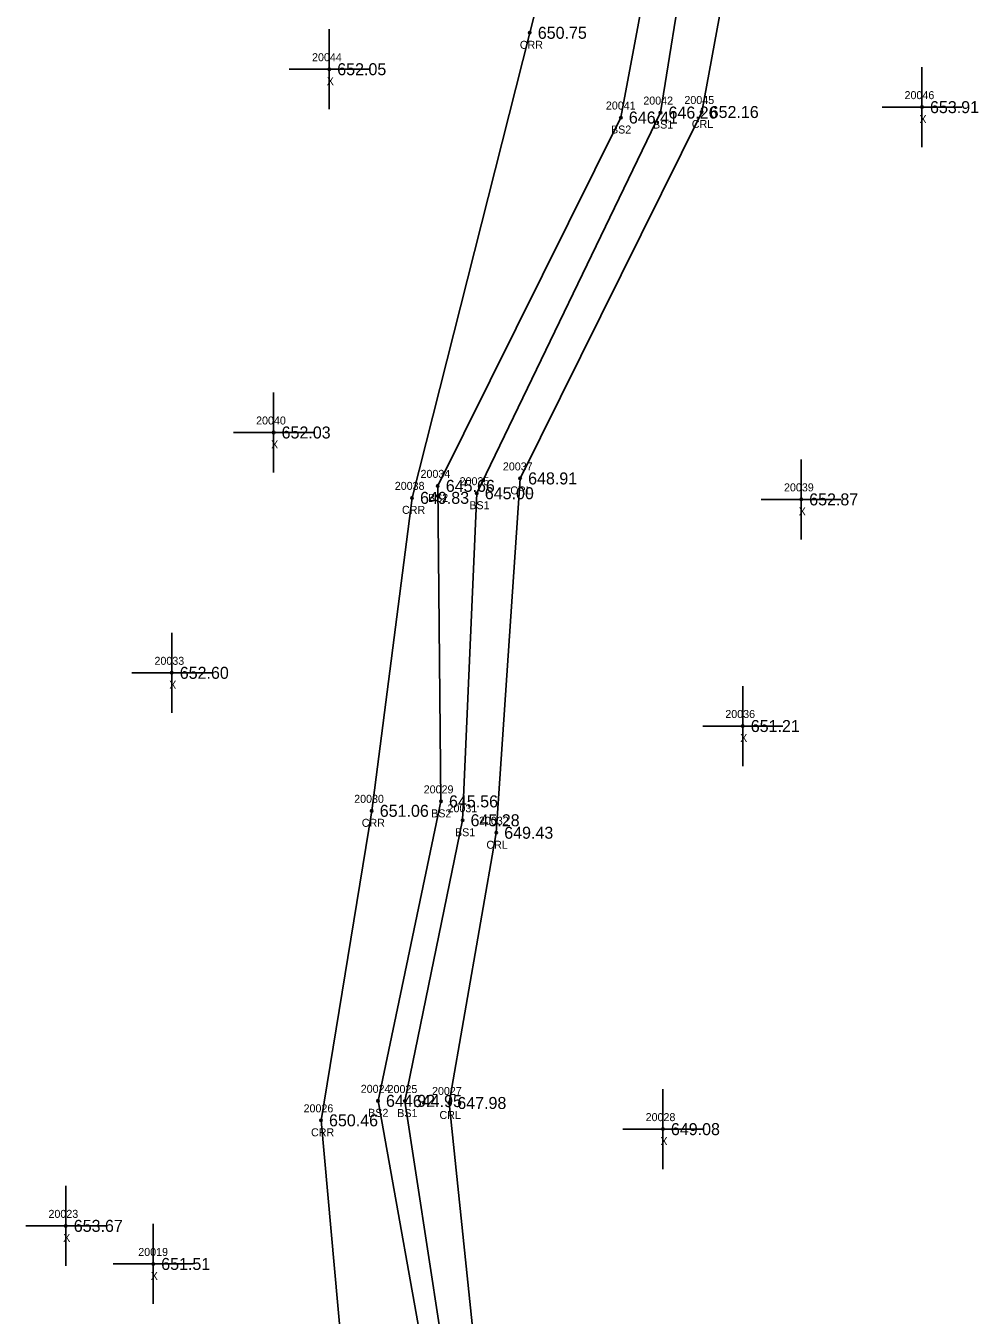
# Model space of a CAD drawing. Extents: x 1655675 to 1657082, y 1004080 to 1005193.
# Drawn here: x 1656333.6 to 1656452.8, y 1004730.1 to 1004891.3 of the extents above; entities that cross this region are included whole.
import ezdxf

# ---------------------------------------------------------------- set-up
doc = ezdxf.new("R2010")
doc.units = 0
for name, color, linetype in [('RD_DTM_BkLn2', 7, 'Continuous'), ('RD_DTM_BkLn_txCode', 7, 'Continuous'), ('RD_EX_H2O', 7, 'Continuous'), ('RD_EX_H2O_txCode', 7, 'Continuous'), ('RD_EX_Misc', 7, 'Continuous'), ('RD_EX_Misc_txCode', 7, 'Continuous'), ('RD_EX_TX_H2O_ELEV', 7, 'Continuous'), ('RD_EX_TX_Misc_ELEV', 7, 'Continuous'), ('RD_SMD_Locator', 7, 'Continuous')]:
    doc.layers.add(name, color=color, linetype=linetype)

msp = doc.modelspace()

# ---------------------------------------------------------------- linework, layer by layer
at = {"layer": 'RD_DTM_BkLn2'}
for points in [[(1656390.72, 1004627.52), (1656382.97, 1004639.34), (1656373.07, 1004660.2), (1656376.96, 1004698.66), (1656386.88, 1004718.9), (1656381.04, 1004756.9), (1656388.26, 1004792), (1656390.04, 1004832.88), (1656413.02, 1004880.46), (1656422.17, 1004937.24), (1656409.91, 1004961.28), (1656410.07, 1005007.08), (1656404.22, 1005036.82), (1656413.87, 1005085.9), (1656434.1, 1005133.63), (1656432.64, 1005179.28)], [(1656378.15, 1004634.61), (1656371.17, 1004659.81), (1656372.69, 1004701.15), (1656384.23, 1004720.35), (1656377.68, 1004756.93), (1656385.56, 1004794.36), (1656385.16, 1004833.8), (1656408.06, 1004879.84), (1656418.86, 1004937.52), (1656406.15, 1004960.8), (1656407.08, 1005007.2), (1656399.18, 1005037.18), (1656409.22, 1005084.89)]]:
    msp.add_lwpolyline(points, dxfattribs=at)
at = {"layer": 'RD_EX_H2O'}
for points in [[(1656396.09, 1004633.07), (1656383.79, 1004647.24), (1656376.78, 1004660.97), (1656381.31, 1004695.03), (1656390.77, 1004716.64), (1656386.6, 1004756.66), (1656392.47, 1004790.44), (1656395.46, 1004834.73), (1656418.17, 1004880.53), (1656428.48, 1004936.46), (1656416.99, 1004968.14), (1656420.24, 1005011.82), (1656412.2, 1005039.74), (1656428.37, 1005086.9), (1656442.1, 1005137.22), (1656437.49, 1005175.75)], [(1656368.16, 1004641.29), (1656363.88, 1004666), (1656364.85, 1004699.99), (1656373.08, 1004726.71), (1656370.55, 1004754.49), (1656376.9, 1004793.18), (1656381.94, 1004832.3), (1656396.67, 1004890.43), (1656408.46, 1004936.92), (1656401.87, 1004961.79), (1656402.89, 1005007.98), (1656396.57, 1005037.78), (1656403.09, 1005084.85)]]:
    msp.add_lwpolyline(points, dxfattribs=at)
at = {"layer": 'RD_EX_Misc'}
for p, q in [((1656371.58, 1004880.88), (1656371.58, 1004890.88)), ((1656366.58, 1004885.88), (1656376.58, 1004885.88)), ((1656445.73, 1004876.14), (1656445.73, 1004886.14)), ((1656440.73, 1004881.14), (1656450.73, 1004881.14)), ((1656364.62, 1004835.47), (1656364.62, 1004845.47)), ((1656359.62, 1004840.47), (1656369.62, 1004840.47)), ((1656430.62, 1004827.11), (1656430.62, 1004837.11)), ((1656425.62, 1004832.11), (1656435.62, 1004832.11)), ((1656351.88, 1004805.43), (1656351.88, 1004815.43)), ((1656346.88, 1004810.43), (1656356.88, 1004810.43)), ((1656423.31, 1004798.78), (1656423.31, 1004808.78)), ((1656418.31, 1004803.78), (1656428.31, 1004803.78)), ((1656413.32, 1004748.39), (1656413.32, 1004758.39)), ((1656408.32, 1004753.39), (1656418.32, 1004753.39)), ((1656338.62, 1004736.3), (1656338.62, 1004746.3)), ((1656349.56, 1004731.54), (1656349.56, 1004741.54)), ((1656333.62, 1004741.3), (1656343.62, 1004741.3)), ((1656344.56, 1004736.54), (1656354.56, 1004736.54))]:
    msp.add_line(p, q, dxfattribs=at)
at = {"layer": 'RD_SMD_Locator'}
for centre in [(1656396.67, 1004890.43), (1656371.58, 1004885.88), (1656413.02, 1004880.46), (1656418.17, 1004880.53), (1656445.73, 1004881.14), (1656408.06, 1004879.84), (1656364.62, 1004840.47), (1656385.16, 1004833.8), (1656395.46, 1004834.73), (1656381.94, 1004832.3), (1656390.04, 1004832.88), (1656430.62, 1004832.11), (1656351.88, 1004810.43), (1656423.31, 1004803.78), (1656376.9, 1004793.18), (1656385.56, 1004794.36), (1656388.26, 1004792), (1656392.47, 1004790.44), (1656377.68, 1004756.93), (1656381.04, 1004756.9), (1656386.6, 1004756.66), (1656370.55, 1004754.49), (1656413.32, 1004753.39), (1656338.62, 1004741.3), (1656349.56, 1004736.54)]:
    msp.add_circle(centre, 0.15, dxfattribs=at)

# ---------------------------------------------------------------- texts
at = {"layer": 'RD_DTM_BkLn_txCode'}
for s, p in [('20041', (1656406.19, 1004880.84)), ('20042', (1656410.87, 1004881.46)), ('BS2', (1656406.83, 1004877.84)), ('BS1', (1656412.08, 1004878.46)), ('20034', (1656383, 1004834.8)), ('20035', (1656387.89, 1004833.88)), ('BS2', (1656383.93, 1004831.8)), ('BS1', (1656389.1, 1004830.88)), ('20029', (1656383.4, 1004795.36)), ('BS2', (1656384.33, 1004792.36)), ('20031', (1656386.38, 1004793)), ('BS1', (1656387.31, 1004790)), ('20024', (1656375.52, 1004757.93)), ('20025', (1656378.88, 1004757.9)), ('BS2', (1656376.45, 1004754.93)), ('BS1', (1656380.09, 1004754.9))]:
    msp.add_text(s, height=1, dxfattribs=at).set_placement(p)
at = {"layer": 'RD_EX_H2O_txCode'}
for s, p in [('CRR', (1656395.42, 1004888.43)), ('20045', (1656416.01, 1004881.53)), ('CRL', (1656416.94, 1004878.53)), ('20037', (1656393.3, 1004835.73)), ('20038', (1656379.78, 1004833.3)), ('CRL', (1656394.23, 1004832.73)), ('CRR', (1656380.68, 1004830.3)), ('20030', (1656374.7, 1004794.18)), ('CRR', (1656375.65, 1004791.18)), ('20032', (1656390.31, 1004791.44)), ('CRL', (1656391.24, 1004788.44)), ('20027', (1656384.44, 1004757.66)), ('20026', (1656368.37, 1004755.49)), ('CRL', (1656385.37, 1004754.66)), ('CRR', (1656369.3, 1004752.49))]:
    msp.add_text(s, height=1, dxfattribs=at).set_placement(p)
at = {"layer": 'RD_EX_Misc_txCode'}
for s, p in [('20044', (1656369.43, 1004886.88)), ('X', (1656371.27, 1004883.88)), ('20046', (1656443.55, 1004882.14)), ('X', (1656445.41, 1004879.14)), ('20040', (1656362.43, 1004841.47)), ('X', (1656364.31, 1004838.47)), ('20039', (1656428.47, 1004833.11)), ('X', (1656430.31, 1004830.11)), ('20033', (1656349.72, 1004811.43)), ('X', (1656351.56, 1004808.43)), ('20036', (1656421.13, 1004804.78)), ('X', (1656422.99, 1004801.78)), ('20028', (1656411.16, 1004754.39)), ('X', (1656413.01, 1004751.39)), ('20023', (1656336.46, 1004742.3)), ('X', (1656338.3, 1004739.3)), ('20019', (1656347.69, 1004737.54)), ('X', (1656349.25, 1004734.54))]:
    msp.add_text(s, height=1, dxfattribs=at).set_placement(p)
at = {"layer": 'RD_EX_TX_H2O_ELEV'}
for s, p in [('650.75', (1656397.67, 1004889.68)), ('652.16', (1656419.17, 1004879.78)), ('648.91', (1656396.46, 1004833.98)), ('649.83', (1656382.94, 1004831.55)), ('651.06', (1656377.9, 1004792.43)), ('649.43', (1656393.47, 1004789.69)), ('647.98', (1656387.6, 1004755.91)), ('650.46', (1656371.55, 1004753.74))]:
    msp.add_text(s, height=1.5, dxfattribs=at).set_placement(p)
at = {"layer": 'RD_EX_TX_Misc_ELEV'}
for s, p in [('652.05', (1656372.58, 1004885.13)), ('653.91', (1656446.73, 1004880.39)), ('646.41', (1656409.06, 1004879.09)), ('646.26', (1656414.02, 1004879.71)), ('652.03', (1656365.62, 1004839.72)), ('645.66', (1656386.16, 1004833.05)), ('645.00', (1656391.04, 1004832.13)), ('652.87', (1656431.62, 1004831.36)), ('652.60', (1656352.88, 1004809.68)), ('651.21', (1656424.31, 1004803.03)), ('645.56', (1656386.56, 1004793.61)), ('645.28', (1656389.26, 1004791.25)), ('644.92', (1656378.68, 1004756.18)), ('644.95', (1656382.04, 1004756.15)), ('649.08', (1656414.32, 1004752.64)), ('653.67', (1656339.62, 1004740.55)), ('651.51', (1656350.56, 1004735.79))]:
    msp.add_text(s, height=1.5, dxfattribs=at).set_placement(p)

doc.saveas('drawing.dxf')
